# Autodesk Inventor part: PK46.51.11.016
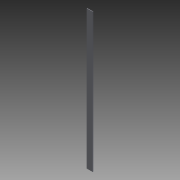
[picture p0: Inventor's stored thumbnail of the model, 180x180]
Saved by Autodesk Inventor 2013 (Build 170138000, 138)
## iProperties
Shininess: 64.0
Length Units: 11269
Angle Units: 11279
Time Units: 11290
Mass Units: 11283
Length Display Precision: 3
Angle Display Precision: 2
Compacted: True
Part Number: PK46.51.11.016
Document SubType Name: Листовой материал
Created: 2005-02
Material: Steel, Mild
Designer: =<Author>
Manufacturer: Standard
Standards Organization: Custom
Description: strip
Density: 7.86 g/cm^3
Sheet Metal Rule: По умолчанию
Mass: 61.8975 g
Surface Area: 115.95 cm^2
Volume: 7.875 cm^3
Density: 0.0
Volumn: 0.0
Area: 0.0
PropertySet Name: Model Information
Control State: 0
Master: False
Checked Out: False
Checked Out Date: 2008-10-15
Last Check In Date: 2008-10-15
Author: PVitaliy
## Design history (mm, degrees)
node "ФлнОтгиб1"
body "Solid1"
sketch "Эскиз1"
  geometry: L1 (0, 0)-(15, 0)
  constraints: 2 end point, 1 horizontal, 1 other
  dimensions: "d0" = 15 distance of L1.start L1.end
feature "Пластина1" dims "d1" = 350, "d2" = 1.5 (= Ширина_просечки), "d4" = 3 (= Минимальный_остаток), "d6" = 1.5 (= Радиус_гибки), "d7" = 1.5, "Толщина" = 1.5
feature "Изгиб1" dims "d2" = 1.5 (= Ширина_просечки), "d3" = 0.75 (= Глубина_просечки), "d4" = 3 (= Минимальный_остаток), "d5" = 1.5 (= Радиус_гибки), "d6" = 1.5 (= Радиус_гибки), "d7" = 1.5, "Толщина" = 1.5, "Зазор_стыка" = 0.01
other parameters: "Радиус_гибки" = 1.5 (= Толщина), "Ширина_просечки" = 1.5 (= Толщина), "Глубина_просечки" = 0.75 (= 0.5 x Толщина), "Размер_высечки" = 6 (= 4 x Толщина), "Минимальный_остаток" = 3 (= 2 x Толщина), "Радиус_перехода" = 1.5 (= Радиус_гибки), "JacobiRadiusSize" = 1.5 (= Толщина), "GapSize" = 1.5 (= Толщина)
